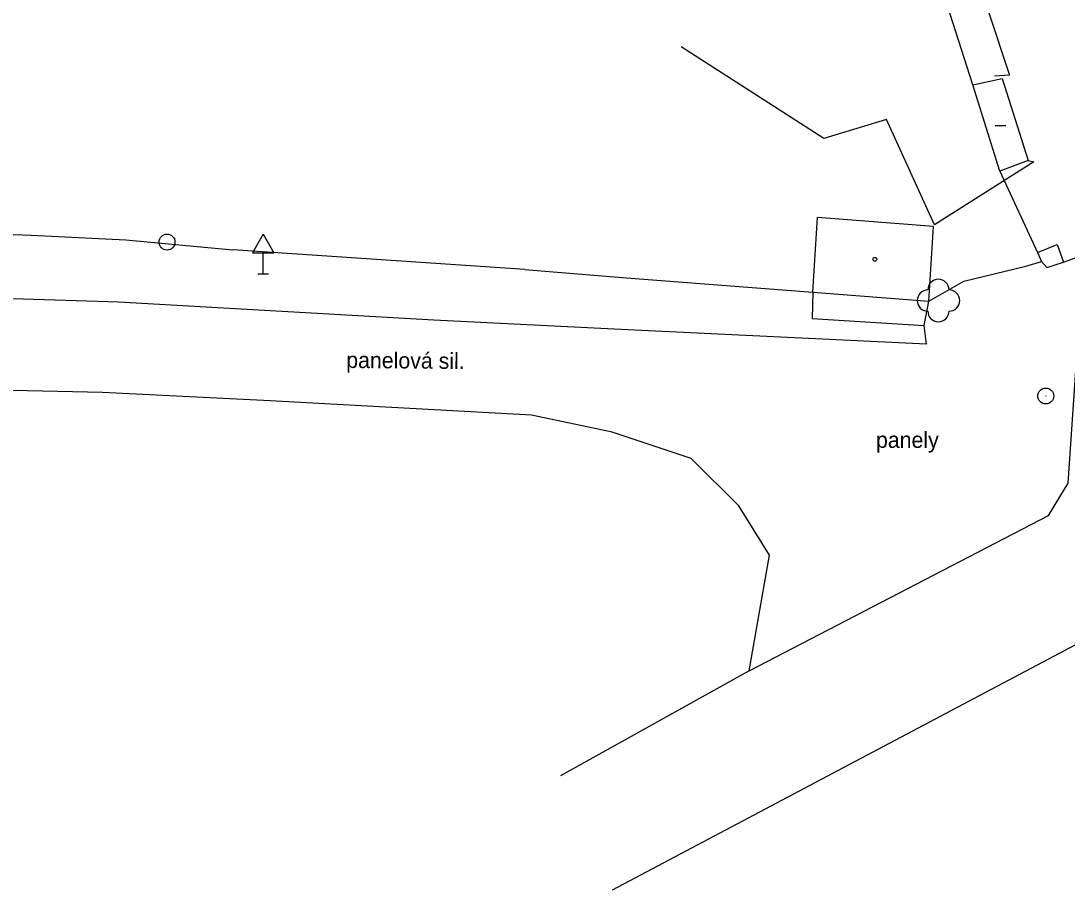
# Model space of a CAD drawing. Extents: x -762500 to -761246, y -1152986 to -1152252.
# Drawn here: x -762351.03 to -762301.8, y -1152963.14 to -1152922.26 of the extents above; entities that cross this region are included whole.
import ezdxf

# ---------------------------------------------------------------- set-up
doc = ezdxf.new("R2010")
doc.units = 0
for name, color, linetype in [('Vrstva 1', 7, 'Continuous'), ('Vrstva 10', 7, 'Continuous'), ('Vrstva 11', 7, 'Continuous'), ('Vrstva 14', 7, 'Continuous'), ('Vrstva 4', 7, 'Continuous'), ('Vrstva 8', 7, 'Continuous'), ('Vrstva 9', 7, 'Continuous')]:
    doc.layers.add(name, color=color, linetype=linetype)

msp = doc.modelspace()

# ---------------------------------------------------------------- linework, layer by layer
at = {"layer": 'Vrstva 1'}
for centre, radius in [((-762344.15, -1152932.66), 0.375), ((-762344.15, -1152932.66), 0.0005), ((-762302.8, -1152939.9), 0.375), ((-762302.8, -1152939.9), 0.0005)]:
    msp.add_circle(centre, radius, dxfattribs=at)
at = {"layer": 'Vrstva 10'}
for p, q in [((-762313.76, -1152935.02), (-762313.8, -1152936.26)), ((-762331.59, -1152936.33), (-762346.43, -1152935.49)), ((-762308.53, -1152936.59), (-762308.31, -1152935.44)), ((-762322.79, -1152936.77), (-762331.59, -1152936.33)), ((-762313.8, -1152936.26), (-762308.53, -1152936.59)), ((-762308.42, -1152937.46), (-762308.53, -1152936.59)), ((-762308.42, -1152937.46), (-762322.79, -1152936.77)), ((-762339.3, -1152940.12), (-762347.18, -1152939.73)), ((-762327, -1152940.8), (-762339.3, -1152940.12)), ((-762323.21, -1152941.6), (-762327, -1152940.8)), ((-762319.49, -1152942.84), (-762323.21, -1152941.6)), ((-762317.25, -1152945.06), (-762319.49, -1152942.84)), ((-762315.8, -1152947.39), (-762317.25, -1152945.06))]:
    msp.add_line(p, q, dxfattribs=at)
for points in [[(-762144.37, -1152867.34), (-762223.5, -1152909.54), (-762245.45, -1152921.4), (-762265.31, -1152932.41), (-762279.87, -1152940.33), (-762294.74, -1152948.08), (-762323.2, -1152963.14)], [(-762303.63, -1152928.83), (-762303.36, -1152928.88), (-762308.03, -1152931.85), (-762310.29, -1152926.89), (-762313.25, -1152927.78), (-762319.95, -1152923.48)], [(-762346.43, -1152935.49), (-762356.39, -1152935.18), (-762376.9, -1152934.77), (-762386.61, -1152934.84), (-762398.4, -1152934.59), (-762408.77, -1152934.59)], [(-762316.75, -1152952.82), (-762302.67, -1152945.52), (-762301.74, -1152944), (-762301.16, -1152935.49), (-762296.04, -1152934.31)], [(-762347.18, -1152939.73), (-762368.41, -1152939.26), (-762372.29, -1152941.27), (-762374.03, -1152942.58), (-762375.2, -1152944.13), (-762376.52, -1152946.79), (-762375.35, -1152946.91), (-762375.34, -1152948.42)], [(-762316.75, -1152952.82), (-762315.8, -1152947.39)], [(-762316.75, -1152952.82), (-762325.64, -1152957.77)]]:
    msp.add_lwpolyline(points, dxfattribs=at)
at = {"layer": 'Vrstva 11'}
msp.add_circle((-762307.85, -1152935.41), 0.0005, dxfattribs=at)
for centre, start, end in [((-762307.85, -1152934.91), 0, 180), ((-762308.35, -1152935.41), 90, 270), ((-762307.35, -1152935.41), 270, 90), ((-762307.85, -1152935.91), 180, 360)]:
    msp.add_arc(centre, 0.5, start, end, dxfattribs=at)
at = {"layer": 'Vrstva 4'}
for p, q in [((-762313.76, -1152935.02), (-762313.54, -1152931.5)), ((-762308.09, -1152931.92), (-762313.54, -1152931.5)), ((-762308.31, -1152935.44), (-762308.09, -1152931.92)), ((-762313.76, -1152935.02), (-762308.31, -1152935.44))]:
    msp.add_line(p, q, dxfattribs=at)
msp.add_lwpolyline([(-762306.24, -1152925.27), (-762304.85, -1152924.97), (-762303.63, -1152928.83), (-762304.96, -1152929.32), (-762306.24, -1152925.27)], dxfattribs=at)
at = {"layer": 'Vrstva 8'}
msp.add_line((-762305.18, -1152927.18), (-762304.68, -1152927.18), dxfattribs=at)
msp.add_circle((-762310.84, -1152933.47), 0.0875, dxfattribs=at)
at = {"layer": 'Vrstva 9'}
for p, q in [((-762346.09, -1152932.56), (-762341.05, -1152933.03)), ((-762339.63, -1152932.294), (-762340.13, -1152933.16)), ((-762339.63, -1152932.294), (-762339.13, -1152933.16)), ((-762327.32, -1152933.95), (-762341.05, -1152933.03)), ((-762340.13, -1152933.16), (-762339.13, -1152933.16)), ((-762339.63, -1152934.16), (-762339.63, -1152933.16)), ((-762327.32, -1152933.95), (-762322.53, -1152934.34)), ((-762339.88, -1152934.16), (-762339.38, -1152934.16)), ((-762322.53, -1152934.34), (-762313.76, -1152935.02))]:
    msp.add_line(p, q, dxfattribs=at)
for points in [[(-762306.24, -1152925.27), (-762313.96, -1152901.15), (-762338.79, -1152917.93), (-762339.38, -1152917.25), (-762341.38, -1152914.91)], [(-762307.69, -1152918.94), (-762306.5, -1152918.78), (-762304.51, -1152924.81), (-762305.21, -1152924.85)], [(-762304.96, -1152929.32), (-762303.19, -1152933.15)], [(-762301.96, -1152933.6), (-762297.02, -1152931.79)], [(-762352.69, -1152932.26), (-762350.55, -1152932.34)], [(-762350.55, -1152932.34), (-762346.09, -1152932.56)], [(-762303.19, -1152933.15), (-762302.27, -1152932.78)], [(-762303.19, -1152933.15), (-762303, -1152933.57)], [(-762302.27, -1152932.78), (-762301.96, -1152933.6)], [(-762303.74, -1152933.79), (-762303, -1152933.57)], [(-762303, -1152933.57), (-762302.75, -1152933.86), (-762301.96, -1152933.6)], [(-762306.65, -1152934.5), (-762303.74, -1152933.79)], [(-762308.31, -1152935.44), (-762306.65, -1152934.5)]]:
    msp.add_lwpolyline(points, dxfattribs=at)

# ---------------------------------------------------------------- texts
at = {"layer": 'Vrstva 14'}
msp.add_text('panelová sil.', height=0.75, rotation=359.4967, dxfattribs=at).set_placement((-762335.72, -1152938.58))
msp.add_text('panely', height=0.75, dxfattribs=at).set_placement((-762310.79, -1152942.34))

doc.saveas('drawing.dxf')
